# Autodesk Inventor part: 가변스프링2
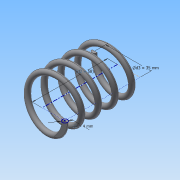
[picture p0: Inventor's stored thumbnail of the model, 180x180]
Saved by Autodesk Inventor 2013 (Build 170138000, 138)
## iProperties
Created: 2015-04
Part Number: 가변스프링2
Material: 일반
Document SubType Name: Modeling
Designer: Administrator
Density: 1 g/cm^3
Author: Administrator
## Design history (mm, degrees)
sketch "스케치1"
  geometry: L1 (0, 0)-(17.5, 0); L2 (17.5, 0)-(17.5, 58); L3 (17.5, 58)-(0, 58); L4 (0, 58)-(0, 0); C1 r 2 at (17.5, 0)
  constraints: 8 end point, 2 parallel, 1 centre point, 1 coincident, 1 horizontal, 1 perpendicular
  dimensions: "d0" = 4 diameter of C1; "d2" = 58 distance of L3.end L1.start (derived); "d3" = 35 diameter of L2 L4
feature "코일1" sketch "스케치1" pitch "d4" = 10; turns "d6" = 4.5; dims "d5" = 58 (= d2), "d7" = 0, angle "d8" = 90 deg, angle "d9" = 90 deg, "d10" = 0, "d11" = 0
sketch "스케치2"
  geometry: L1 (-19.5, 0)-(-15.5, 0) reference; 1 further point
  constraints: 1 horizontal alignment
extrude "돌출1" cut sketch "스케치2" distance "d12" = 10; taper "d13" = 0 deg
node "작업 평면1"
sketch "스케치3"
  geometry: L1 (15.5, 0)-(19.5, 0) reference; 1 further point
  constraints: 1 horizontal alignment
extrude "돌출2" cut sketch "스케치3" distance "d15" = 10; taper "d16" = 0 deg
node "솔리드1"
node "절단 모서리 투영1"
node "절단 모서리 투영2"
other parameters: "d14" = 58 (= d2)
